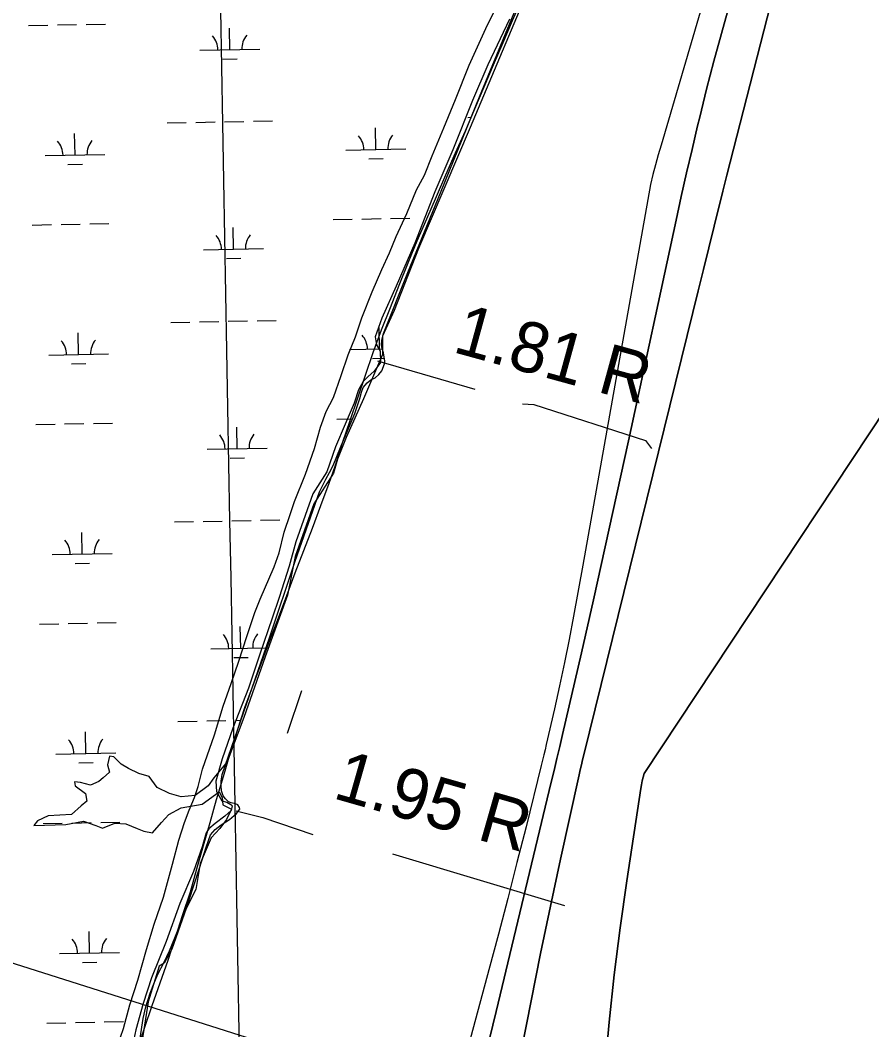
# Model space of a CAD drawing. Extents: x 3925854 to 3964121, y 224593 to 250589.
# Drawn here: x 3940345 to 3941766, y 232780 to 234463 of the extents above; entities that cross this region are included whole.
import ezdxf

# ---------------------------------------------------------------- set-up
doc = ezdxf.new("R2010")
doc.units = 0
for name, color, linetype in [('V-GRID-MAJR', 7, 'Continuous'), ('V-LEVE-TOET', 7, 'Continuous'), ('V-RIVR-EDGE', 7, 'Continuous'), ('V-RIVR-JETY', 7, 'Continuous'), ('V-RIVR-RANG-IDEN', 7, 'Continuous'), ('V-RRAP-FSHR', 7, 'Continuous'), ('V-TOPO-DPTH', 7, 'Continuous'), ('V-TOPO-MINR', 7, 'Continuous'), ('V-UTIL-LINE', 7, 'Continuous'), ('V-WETL-SWMP', 7, 'Continuous')]:
    doc.layers.add(name, color=color, linetype=linetype)

msp = doc.modelspace()

# ---------------------------------------------------------------- linework, layer by layer
at = {"layer": 'V-GRID-MAJR'}
msp.add_spline([(3940756.893, 230221.23), (3940647.643, 236278.076), (3940538.337, 242338.005), (3940429.031, 248397.924), (3940428.975, 248401.018)], degree=3, dxfattribs=at)
at = {"layer": 'V-LEVE-TOET'}
for p, q in [((3940941.641, 233895.337), (3941103.87, 233847.86)), ((3940966.582, 233073.335), (3941253.73, 232986.78))]:
    msp.add_line(p, q, dxfattribs=at)
for points in [[(3941183.66, 233823.612), (3941202.09, 233822.313), (3941388.398, 233762.395), (3941398.763, 233749.081)], [(3940705.585, 233144.786), (3940750.235, 233133.653), (3940833.665, 233105.667)]]:
    msp.add_lwpolyline(points, dxfattribs=at)
at = {"layer": 'V-RIVR-EDGE'}
msp.add_lwpolyline([(3941208.811, 234552.453), (3941096.202, 234284.24), (3941010.21, 234082.569), (3940969.262, 233979.174), (3940949.811, 233936.178), (3940949.811, 233905.467), (3940918.076, 233831.76), (3940889.412, 233767.266), (3940875.08, 233731.436), (3940867.914, 233707.89), (3940835.156, 233656.705), (3940804.444, 233568.665), (3940791.136, 233504.172), (3940754.282, 233401.8), (3940718.452, 233300.453), (3940690.812, 233226.745), (3940668.291, 233200.129), (3940659.077, 233186.821), (3940637.579, 233170.441), (3940614.034, 233168.394), (3940594.583, 233173.512), (3940574.109, 233183.75), (3940560.801, 233202.176), (3940543.398, 233207.295), (3940525.994, 233215.485), (3940513.71, 233222.651), (3940501.425, 233234.935), (3940494.259, 233235.959), (3940491.188, 233221.627), (3940494.259, 233209.342), (3940484.022, 233200.129), (3940476.856, 233193.987), (3940462.524, 233187.844), (3940446.145, 233191.939), (3940435.908, 233192.963), (3940436.931, 233186.821), (3940454.335, 233173.512), (3940456.382, 233161.228), (3940447.169, 233153.038), (3940430.789, 233138.706), (3940391.888, 233136.659), (3940374.485, 233128.469), (3940368.343, 233120.279), (3940421.576, 233122.327), (3940451.263, 233127.445), (3940471.738, 233120.279), (3940482.999, 233116.185), (3940503.473, 233124.374), (3940521.9, 233123.351), (3940540.326, 233115.161), (3940551.587, 233111.066), (3940565.919, 233107.995), (3940581.275, 233125.398), (3940593.559, 233138.706), (3940614.034, 233149.967), (3940648.84, 233156.109), (3940677.504, 233176.584), (3940682.622, 233167.37), (3940683.646, 233155.086), (3940697.978, 233147.92), (3940689.788, 233130.516), (3940678.528, 233115.161), (3940664.196, 233099.805), (3940645.769, 233056.809), (3940638.603, 233013.813), (3940622.223, 232982.078), (3940598.678, 232914.513), (3940585.37, 232890.968), (3940577.18, 232885.849), (3940558.753, 232826.474), (3940539.303, 232702.605)], dxfattribs=at)
at = {"layer": 'V-RIVR-JETY'}
for points in [[(3940507.887, 232752.87), (3940517.654, 232782.052), (3940528.337, 232821.386), (3940541.782, 232862.637), (3940556.136, 232913.644), (3940568.815, 232956.077), (3940584.65, 233000.813), (3940599.453, 233056.115), (3940610.144, 233095.838), (3940619.524, 233125.418), (3940627.613, 233146.025), (3940636.1, 233167.017), (3940642.209, 233185.694), (3940649.621, 233214.129), (3940669.536, 233271.706), (3940683.845, 233319.199), (3940697.243, 233356.932), (3940710.244, 233394.279), (3940723.689, 233435.53), (3940737.12, 233475.607), (3940745.619, 233497.773), (3940769.003, 233551.789), (3940777.517, 233574.735), (3940785.793, 233609.407), (3940795.957, 233638.976), (3940803.281, 233660.767), (3940821.471, 233706.253), (3940836.497, 233749.046), (3940846.348, 233784.48), (3940855.683, 233810.541), (3940868.108, 233833.827), (3940881.098, 233870.392), (3940892.502, 233905.026), (3940904.63, 233935.35), (3940915.599, 233966.863), (3940932.585, 234010.021), (3940948.713, 234047.327), (3940961.587, 234074.903), (3940972.505, 234102.508), (3940990.597, 234140.57), (3941006.366, 234180.226), (3941019.977, 234204.669), (3941032.521, 234236.941), (3941052.291, 234283.578), (3941071.675, 234330.612), (3941094.326, 234388.155), (3941124.919, 234455.364), (3941153.013, 234510.879)], [(3941161.781, 234464.646), (3941125.597, 234388.522), (3941100.185, 234329.062), (3941067.44, 234247.029), (3941037.195, 234176.691), (3941003.626, 234091.543), (3940972.578, 234019.65), (3940948.813, 233966.423), (3940937.453, 233934.914), (3940940.011, 233921.592), (3940946.131, 233911.35), (3940946.272, 233892.588), (3940935.915, 233877.873), (3940925.626, 233868.24), (3940917.706, 233860.529), (3940909.711, 233846.955), (3940902.375, 233824.384), (3940887.847, 233789.793), (3940871.317, 233751.71), (3940857.088, 233710.081), (3940845.115, 233691.479), (3940833.54, 233673.264), (3940820.945, 233637.082), (3940805.124, 233593.519), (3940794.03, 233552.628), (3940777.703, 233500.472), (3940765.911, 233465.846), (3940745.189, 233406.323), (3940726.458, 233349.51), (3940700.166, 233282.634), (3940682.295, 233231.672), (3940672.026, 233194.29), (3940672.972, 233177.081), (3940681.756, 233161.721), (3940690.323, 233159.263), (3940696.92, 233155.656), (3940698.843, 233153.287), (3940697.176, 233145.492), (3940686.887, 233135.858), (3940670.703, 233123.957), (3940660.42, 233114.713), (3940655.642, 233108.133), (3940649.078, 233084.769), (3940634.468, 233043.926), (3940611.87, 232990.291), (3940589.148, 232927.278), (3940564.502, 232866.634), (3940550.647, 232823.825), (3940538.339, 232779.826), (3940528.339, 232733.058)]]:
    msp.add_lwpolyline(points, dxfattribs=at)
at = {"layer": 'V-RRAP-FSHR'}
for points in [[(3941182.56, 234498.524), (3941166.262, 234461.773), (3941150.468, 234425.23), (3941134.674, 234388.274), (3941118.879, 234351.525), (3941103.12, 234314.806), (3941087.66, 234278.122), (3941071.12, 234241.436), (3941055.176, 234204.753), (3941039.231, 234168.679), (3941023.285, 234131.383), (3941007.431, 234094.66), (3940991.903, 234057.796), (3940976.867, 234020.734), (3940962.91, 233983.562), (3940947.597, 233946.285), (3940933.849, 233908.72), (3940920.774, 233870.918), (3940908.109, 233832.977), (3940895.461, 233795.28), (3940882.817, 233757.799)], [(3940882.817, 233757.799), (3940870.168, 233719.133), (3940860.321, 233690.576), (3940846.2, 233653.15), (3940832.79, 233615.725), (3940817.959, 233578.3), (3940803.836, 233540.877), (3940789.715, 233503.454), (3940775.594, 233466.281), (3940761.473, 233428.604), (3940747.352, 233391.181), (3940733.358, 233353.708), (3940719.886, 233316.449), (3940707.246, 233278.971), (3940695.343, 233239.911), (3940683.835, 233201.603), (3940672.548, 233163.23), (3940661.563, 233124.768), (3940650.58, 233086.305), (3940639.508, 233047.868), (3940628.92, 233009.532), (3940616.181, 232971.349), (3940603.924, 232933.272), (3940591.63, 232895.397), (3940578.187, 232857.527), (3940565.309, 232819.655), (3940552.433, 232781.786), (3940539.558, 232743.914)]]:
    msp.add_lwpolyline(points, dxfattribs=at)
at = {"layer": 'V-TOPO-DPTH'}
for points in [[(3941764.947, 235143.923), (3941524.526, 234204.825), (3941522.799, 234198.049), (3941521.079, 234191.271), (3941519.373, 234184.49), (3941517.674, 234177.707), (3941503.148, 234119.449), (3941494.208, 234083.531), (3941485.288, 234047.608), (3941476.398, 234011.678), (3941467.529, 233975.742), (3941285.814, 233238.152), (3941283.785, 233229.787), (3941281.796, 233221.414), (3941279.866, 233213.026), (3941277.976, 233204.629), (3941246.919, 233064.333), (3941229.918, 232985.702), (3941213.436, 232906.965), (3941197.73, 232828.069), (3941182.541, 232749.068)], [(3941182.541, 232749.068), (3941197.73, 232828.069), (3941213.436, 232906.965), (3941229.918, 232985.702), (3941246.919, 233064.333), (3941277.976, 233204.629), (3941279.866, 233213.026), (3941281.796, 233221.414), (3941283.785, 233229.787), (3941285.814, 233238.152), (3941467.529, 233975.742), (3941476.398, 234011.678), (3941485.288, 234047.608), (3941494.208, 234083.531), (3941503.148, 234119.449), (3941517.674, 234177.707), (3941519.373, 234184.49), (3941521.079, 234191.271), (3941522.799, 234198.049), (3941524.526, 234204.825), (3941764.947, 235143.923)], [(3941117.196, 232719.318), (3941139.38, 232810.562), (3941231.51, 233192.549), (3941236.256, 233212.367), (3941240.961, 233232.195), (3941245.604, 233252.037), (3941250.205, 233271.89), (3941281.631, 233408.469), (3941301.731, 233496.66), (3941321.586, 233584.904), (3941341.075, 233673.231), (3941360.321, 233761.611), (3941439.659, 234129.635), (3941448.299, 234169.019), (3941457.127, 234208.36), (3941466.239, 234247.636), (3941475.54, 234286.868), (3941479.093, 234301.618), (3941490.636, 234348.107), (3941502.61, 234394.481), (3941515.232, 234440.684), (3941528.284, 234486.772)], [(3941935.3, 234034.948), (3941386.319, 233206.852), (3941384.696, 233200.765), (3941383.23, 233194.643), (3941382.001, 233188.47), (3941380.93, 233182.262), (3941357.364, 233028.05), (3941346.261, 232949.708), (3941336.292, 232871.235), (3941328.026, 232792.565), (3941320.894, 232713.763)], [(3941320.894, 232713.763), (3941328.026, 232792.565), (3941336.292, 232871.235), (3941346.261, 232949.708), (3941357.364, 233028.05), (3941380.93, 233182.262), (3941382.001, 233188.47), (3941383.23, 233194.643), (3941384.696, 233200.765), (3941386.319, 233206.852), (3941935.3, 234034.948)]]:
    msp.add_lwpolyline(points, dxfattribs=at)
at = {"layer": 'V-TOPO-MINR'}
for points in [[(3941764.947, 235143.923), (3941524.526, 234204.825), (3941522.799, 234198.049), (3941521.079, 234191.271), (3941519.373, 234184.49), (3941517.674, 234177.707), (3941503.148, 234119.449), (3941494.208, 234083.531), (3941485.288, 234047.608), (3941476.398, 234011.678), (3941467.529, 233975.742), (3941285.814, 233238.152), (3941283.785, 233229.787), (3941281.796, 233221.414), (3941279.866, 233213.026), (3941277.976, 233204.629), (3941246.919, 233064.333), (3941229.918, 232985.702), (3941213.436, 232906.965), (3941197.73, 232828.069), (3941182.541, 232749.068)], [(3941565.157, 234767.24), (3941414.657, 234254.898), (3941409.975, 234238.538), (3941405.446, 234222.136), (3941401.147, 234205.673), (3941397.002, 234189.169), (3941284.112, 233554.268), (3941268.477, 233469.308), (3941261.097, 233430.576), (3941253.393, 233391.912), (3941245.203, 233353.347), (3941236.688, 233314.849), (3941223.196, 233255.615), (3941221.157, 233246.791), (3941219.083, 233237.975), (3941216.953, 233229.173), (3941214.788, 233220.378), (3941189.322, 233118.32), (3941174.231, 233058.547), (3941158.92, 232998.83), (3941143.278, 232939.199), (3941127.416, 232879.626), (3940982.328, 232340.733)], [(3941528.284, 234486.772), (3941515.232, 234440.684), (3941502.61, 234394.481), (3941490.636, 234348.107), (3941479.093, 234301.618), (3941475.54, 234286.868), (3941466.239, 234247.636), (3941457.127, 234208.36), (3941448.299, 234169.019), (3941439.659, 234129.635), (3941360.321, 233761.611), (3941341.075, 233673.231), (3941321.586, 233584.904), (3941301.731, 233496.66), (3941281.631, 233408.469), (3941250.205, 233271.89), (3941245.604, 233252.037), (3941240.961, 233232.195), (3941236.256, 233212.367), (3941231.51, 233192.549), (3941139.38, 232810.562), (3941117.196, 232719.318)], [(3941935.3, 234034.948), (3941386.319, 233206.852), (3941384.696, 233200.765), (3941383.23, 233194.643), (3941382.001, 233188.47), (3941380.93, 233182.262), (3941357.364, 233028.05), (3941346.261, 232949.708), (3941336.292, 232871.235), (3941328.026, 232792.565), (3941320.894, 232713.763)], [(3940814.92, 233344.7), (3940790.997, 233273.74)]]:
    msp.add_lwpolyline(points, dxfattribs=at)
at = {"layer": 'V-UTIL-LINE'}
msp.add_lwpolyline([(3944448.956, 231161.167), (3944066.619, 231705.838), (3939716.974, 233085.703), (3938914.857, 233883.421)], dxfattribs=at)
at = {"layer": 'V-WETL-SWMP'}
for p, q in [((3941111.843, 234335.161), (3941182.682, 234507.538)), ((3940359.536, 234454.186), (3940391.531, 234454.768)), ((3940407.528, 234455.059), (3940439.523, 234455.641)), ((3940455.52, 234455.932), (3940487.515, 234456.514)), ((3940695.169, 234413.852), (3940694.515, 234449.846)), ((3940645.177, 234412.943), (3940745.161, 234414.761)), ((3941147.002, 234422.067), (3941147.562, 234422.078)), ((3940683.452, 234398.205), (3940707.448, 234398.641)), ((3941047.567, 234178.176), (3941111.843, 234335.161)), ((3940590.526, 234291.858), (3940622.52, 234292.44)), ((3940638.518, 234292.731), (3940670.512, 234293.312)), ((3940686.51, 234293.603), (3940718.504, 234294.185)), ((3940734.502, 234294.476), (3940766.496, 234295.058)), ((3941092.351, 234300.983), (3941097.89, 234301.084)), ((3940436.882, 234238.314), (3940436.227, 234274.308)), ((3940938.707, 234247.439), (3940938.052, 234283.433)), ((3940888.715, 234246.53), (3940988.698, 234248.348)), ((3940386.89, 234237.405), (3940486.873, 234239.223)), ((3940926.989, 234231.792), (3940950.985, 234232.228)), ((3940425.164, 234222.667), (3940449.16, 234223.104)), ((3940992.416, 234042.355), (3941047.567, 234178.176)), ((3940413.576, 234122.439), (3940445.571, 234123.021)), ((3940461.568, 234123.312), (3940493.563, 234123.894)), ((3940867.409, 234130.691), (3940899.404, 234131.273)), ((3940915.401, 234131.564), (3940947.396, 234132.146)), ((3940963.393, 234132.436), (3940995.388, 234133.018)), ((3940365.584, 234121.566), (3940397.579, 234122.148)), ((3940701.217, 234081.232), (3940700.563, 234117.226)), ((3940651.225, 234080.323), (3940751.209, 234082.141)), ((3940689.5, 234065.585), (3940713.496, 234066.021)), ((3940951.819, 233940.894), (3940992.416, 234042.355)), ((3940596.574, 233959.238), (3940628.568, 233959.82)), ((3940644.566, 233960.111), (3940676.56, 233960.692)), ((3940692.558, 233960.983), (3940724.552, 233961.565)), ((3940740.55, 233961.856), (3940772.545, 233962.438)), ((3940442.93, 233905.694), (3940442.275, 233941.688)), ((3940944.755, 233914.819), (3940944.1, 233950.813)), ((3940948.894, 233928.77), (3940951.819, 233940.894)), ((3940948.25, 233921.868), (3940948.894, 233928.77)), ((3940949.271, 233915.497), (3940948.25, 233921.868)), ((3940392.938, 233904.785), (3940492.921, 233906.603)), ((3940894.763, 233913.91), (3940949.475, 233914.905)), ((3940951.667, 233908.555), (3940949.271, 233915.497)), ((3940953.694, 233894.707), (3940951.667, 233908.555)), ((3940431.212, 233890.047), (3940455.208, 233890.484)), ((3940933.037, 233899.172), (3940952.987, 233899.535)), ((3940948.78, 233878.463), (3940953.083, 233890.292)), ((3940953.083, 233890.292), (3940953.694, 233894.707)), ((3940937.567, 233866.726), (3940943.725, 233872.449)), ((3940943.725, 233872.449), (3940948.78, 233878.463)), ((3940917.725, 233850.403), (3940924.464, 233858.33)), ((3940924.464, 233858.33), (3940930.61, 233863.224)), ((3940930.61, 233863.224), (3940937.567, 233866.726)), ((3940912.236, 233832.509), (3940914.859, 233842.702)), ((3940914.859, 233842.702), (3940917.725, 233850.403)), ((3940903.607, 233807.192), (3940912.236, 233832.509)), ((3940881.056, 233753.313), (3940903.607, 233807.192)), ((3940371.632, 233788.946), (3940403.627, 233789.528)), ((3940419.624, 233789.819), (3940451.619, 233790.401)), ((3940467.617, 233790.692), (3940499.611, 233791.274)), ((3940873.457, 233798.071), (3940899.991, 233798.554)), ((3940707.265, 233748.612), (3940706.611, 233784.606)), ((3940873.908, 233735.44), (3940881.056, 233753.313)), ((3940657.273, 233747.703), (3940757.257, 233749.521)), ((3940867.634, 233720.873), (3940873.908, 233735.44)), ((3940695.548, 233732.965), (3940719.544, 233733.401)), ((3940861.668, 233708.79), (3940867.634, 233720.873)), ((3940855.169, 233698.095), (3940861.668, 233708.79)), ((3940844.657, 233676.674), (3940855.169, 233698.095)), ((3940804.153, 233561.39), (3940844.657, 233676.674)), ((3940602.622, 233626.618), (3940634.616, 233627.2)), ((3940650.614, 233627.491), (3940682.608, 233628.072)), ((3940698.606, 233628.363), (3940730.601, 233628.945)), ((3940746.598, 233629.236), (3940778.593, 233629.818)), ((3940448.978, 233573.074), (3940448.323, 233609.068)), ((3940398.986, 233572.165), (3940498.969, 233573.983)), ((3940437.26, 233557.427), (3940461.256, 233557.864)), ((3940761.269, 233433.423), (3940804.153, 233561.39)), ((3940377.68, 233456.326), (3940409.675, 233456.908)), ((3940425.672, 233457.199), (3940457.667, 233457.781)), ((3940473.665, 233458.072), (3940505.659, 233458.653)), ((3940713.313, 233415.992), (3940712.659, 233451.986)), ((3940708.667, 233281.259), (3940761.269, 233433.423)), ((3940663.321, 233415.083), (3940755.508, 233416.759)), ((3940701.596, 233400.345), (3940725.592, 233400.781)), ((3940608.67, 233293.998), (3940640.664, 233294.58)), ((3940656.662, 233294.871), (3940688.657, 233295.452)), ((3940682.505, 233205.314), (3940708.667, 233281.259)), ((3940704.654, 233295.743), (3940713.731, 233295.908)), ((3940455.026, 233240.454), (3940454.371, 233276.448)), ((3940405.034, 233239.545), (3940505.018, 233241.363)), ((3940443.308, 233224.807), (3940467.304, 233225.244)), ((3940680.977, 233194.277), (3940682.505, 233205.314)), ((3940680.609, 233187.371), (3940680.977, 233194.277)), ((3940681.313, 233177.964), (3940680.609, 233187.371)), ((3940683.971, 233169.912), (3940681.313, 233177.964)), ((3940687.77, 233164.61), (3940683.971, 233169.912)), ((3940692.963, 233160.118), (3940687.77, 233164.61)), ((3940697.635, 233158.121), (3940692.963, 233160.118)), ((3940704.523, 233156.371), (3940697.635, 233158.121)), ((3940708.646, 233154.658), (3940704.523, 233156.371)), ((3940706.245, 233140.316), (3940711.591, 233147.432)), ((3940711.079, 233150.48), (3940708.646, 233154.658)), ((3940711.591, 233147.432), (3940711.079, 233150.48)), ((3940680.838, 233121.303), (3940694.505, 233130.521)), ((3940694.505, 233130.521), (3940706.245, 233140.316)), ((3940383.728, 233123.706), (3940415.723, 233124.288)), ((3940431.721, 233124.579), (3940463.715, 233125.161)), ((3940479.713, 233125.452), (3940511.707, 233126.033)), ((3940662.927, 233104.679), (3940670.513, 233113.977)), ((3940670.513, 233113.977), (3940680.838, 233121.303)), ((3940655.47, 233084.323), (3940662.927, 233104.679)), ((3940644.775, 233049.083), (3940655.47, 233084.323)), ((3940626.638, 232994.592), (3940644.775, 233049.083)), ((3940615.445, 232963.504), (3940626.638, 232994.592)), ((3940603.431, 232932.981), (3940615.445, 232963.504)), ((3940461.074, 232907.834), (3940460.419, 232943.828)), ((3940594.577, 232911.537), (3940603.431, 232932.981)), ((3940585.186, 232891.207), (3940594.577, 232911.537)), ((3940411.082, 232906.925), (3940511.066, 232908.743)), ((3940449.356, 232892.187), (3940473.352, 232892.624)), ((3940575.831, 232873.64), (3940585.186, 232891.207)), ((3940569.284, 232859.353), (3940575.831, 232873.64)), ((3940562.125, 232840.651), (3940569.284, 232859.353)), ((3940555.192, 232818.076), (3940562.125, 232840.651)), ((3940550.79, 232798.785), (3940555.192, 232818.076)), ((3940485.761, 232792.832), (3940517.755, 232793.413)), ((3940545.375, 232765.686), (3940550.79, 232798.785)), ((3940389.777, 232791.086), (3940421.771, 232791.668)), ((3940437.769, 232791.959), (3940469.763, 232792.541))]:
    msp.add_line(p, q, dxfattribs=at)
for centre, start, end in [((3940639.927, 234413.322), 0.269879, 41.813537), ((3940750.394, 234415.331), 140.269876, 181.813534), ((3940381.639, 234237.784), 0.269879, 41.813537), ((3940492.107, 234239.793), 140.269876, 181.813534), ((3940883.464, 234246.909), 0.269879, 41.813537), ((3940993.932, 234248.918), 140.269876, 181.813534), ((3940645.975, 234080.702), 0.269879, 41.813537), ((3940756.442, 234082.711), 140.269876, 181.813534), ((3940889.512, 233914.289), 0.269879, 41.813537), ((3940387.687, 233905.164), 0.269879, 41.813537), ((3940498.155, 233907.173), 140.269876, 181.813534), ((3940652.023, 233748.082), 0.269879, 41.813537), ((3940762.49, 233750.091), 140.269876, 181.813534), ((3940393.735, 233572.544), 0.269879, 41.813537), ((3940504.203, 233574.553), 140.269876, 181.813534), ((3940658.071, 233415.462), 0.269879, 41.813537), ((3940768.538, 233417.471), 140.269876, 181.813534), ((3940510.251, 233241.933), 140.269876, 181.813534), ((3940399.783, 233239.924), 0.269879, 41.813537), ((3940405.831, 232907.304), 0.269879, 41.813537), ((3940516.299, 232909.313), 140.269876, 181.813534)]:
    msp.add_arc(centre, 35.246, start, end, dxfattribs=at)

# ---------------------------------------------------------------- texts
at = {"layer": 'V-RIVR-RANG-IDEN'}
for s, rotation, p in [('1.81 R', 344.619537, (3941064.963, 233910.307)), ('1.95 R', 344.068909, (3940865.077, 233166.512))]:
    msp.add_text(s, height=84, rotation=rotation, dxfattribs=at).set_placement(p)

doc.saveas('drawing.dxf')
